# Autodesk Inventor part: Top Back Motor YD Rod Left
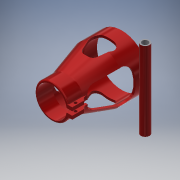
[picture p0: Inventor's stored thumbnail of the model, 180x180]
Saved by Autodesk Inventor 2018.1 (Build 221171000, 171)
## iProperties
Created: 2018-06
Part Number: Top Back Motor YD Rod Left
Material: Generic
Document SubType Name: Modeling
Designer: Ryan
Density: 1 g/cm^3
Appearance: Default
Author: Ryan
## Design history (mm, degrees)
derived "Assembly3 Part out.iam"
sketch "Sketch1"
  geometry: L1 (-38.527, 77.015)-(136.232, 77.015); L2 (136.232, 77.015)-(136.232, -217.058); L3 (136.232, -217.058)-(-38.527, -217.058); L4 (-38.527, -217.058)-(-38.527, 77.015); 1 further point
  constraints: 8 end point, 2 parallel, 1 horizontal, 1 perpendicular
extrude "Extrusion1" cut sketch "Sketch1" distance "d1" = 25.4; taper "d2" = 0 deg
workplane "Work Plane2"
  workplane "Work Plane1"
workpoint "Work Point1"
workplane "Work Plane3"
workplane "Work Plane4"
workplane "Work Plane5"
workplane "Work Plane6"
workplane "Work Plane7"
workplane "Work Plane8"
workplane "Work Plane9"
workplane "Work Plane10"
workplane "Work Plane11"
workplane "Work Plane12"
sketch "Sketch2"
  geometry: L1 (-120.064, -229.344)-(13.991, -229.344); L2 (13.991, -229.344)-(13.991, 75.966); L3 (13.991, 75.966)-(-120.064, 75.966); L4 (-120.064, 75.966)-(-120.064, -229.344); 1 further point
  constraints: 8 end point, 2 parallel, 1 horizontal, 1 perpendicular
extrude "Extrusion2" cut sketch "Sketch2" distance "d10" = 25.4; taper "d11" = 0 deg
sketch "Sketch3"
  geometry: C1 r 103.315 at (-49.509, 32.992); 1 further point
  constraints: 1 centre point
extrude "Extrusion3" cut sketch "Sketch3" distance "d12" = 106.3625; taper "d13" = 0 deg
sketch "Sketch4"
  geometry: C1 r 4.763 at (0, 0) reference; C2 r 3.429 at (0, 0); C3 r 4.763 at (101.6, 0) reference; C4 r 3.429 at (101.6, 0); 1 further point
  constraints: 2 centre point, 2 coincident
  dimensions: "d14" = 6.858 diameter of C2; "d15" = 6.858 diameter of C4
extrude "Extrusion4" cut sketch "Sketch4" distance "d16" = 12.7; taper "d17" = 0 deg
sketch "Sketch5"
  geometry: C1 r 4.763 at (0, 0) reference; C2 r 3.429 at (0, 0); C3 r 4.763 at (-101.6, 0) reference; C4 r 3.429 at (-101.6, 0); 1 further point
  constraints: 2 centre point, 2 coincident
  dimensions: "d18" = 6.858 diameter of C2; "d19" = 6.858 diameter of C4
extrude "Extrusion5" cut sketch "Sketch5" distance "d20" = 15.875; taper "d21" = 0 deg
sketch "Sketch7"
  geometry: L1 (-66.992, 48.982)-(58.965, 48.982); L2 (58.965, 48.982)-(58.965, -67.111); L3 (58.965, -67.111)-(-66.992, -67.111); L4 (-66.992, -67.111)-(-66.992, 48.982); 1 further point
  constraints: 8 end point, 2 parallel, 1 horizontal, 1 perpendicular
extrude "Extrusion6" cut sketch "Sketch7" distance "d22" = 150.8125; taper "d23" = 0 deg
sketch "Sketch8"
  geometry: C1 r 3.429 at (0, 0) reference; C2 r 3.429 at (0, 0); C3 r 4.763 at (0, 0); 1 further point
  constraints: 2 centre point, 2 coincident
extrude "Extrusion7" join sketch "Sketch8" distance "d24" = 9.525; taper "d25" = 0 deg
body "Solid1"
node "Rov v4.2.ipt:1" dims "d0" = 10
node "Motor mount.ipt:1" dims "d0" = 10
node "Motor mount.ipt:2" dims "d0" = 10
node "Motor mount_MIR2.ipt:1" dims "d0" = 10
other parameters: "d3" = 6.35, "d4" = 12.7, "d5" = -12.7, "d6" = 12.7, "d7" = -12.7, "d8" = 6.35, "d9" = -6.35
